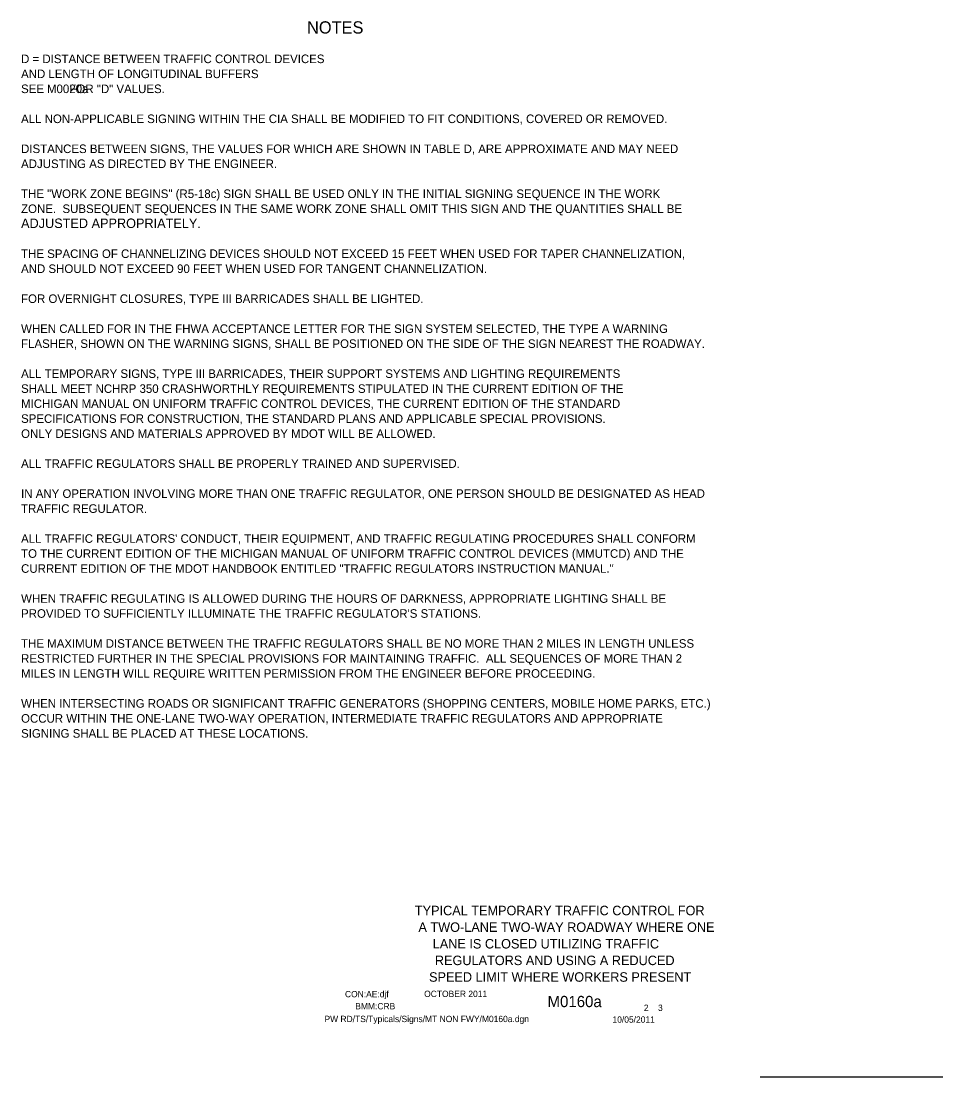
# Model space of a CAD drawing. Extents: x 16735 to 19510, y 5880 to 6929.
# Drawn here: x 17802 to 18706, y 5880 to 6915 of the extents above; entities that cross this region are included whole.
import ezdxf

# ---------------------------------------------------------------- set-up
doc = ezdxf.new("R2010")
doc.units = 0
doc.layers.add('Level 10', color=7, linetype='Continuous')
doc.layers.add('TRAFFIC_SIGNS_PR', color=7, linetype='Continuous')

msp = doc.modelspace()

# ---------------------------------------------------------------- linework, layer by layer
at = {"layer": 'TRAFFIC_SIGNS_PR'}
msp.add_line((18526.8, 5880), (18705.8, 5880), dxfattribs=at)

# ---------------------------------------------------------------- texts
at = {"layer": 'Level 10'}
for s, height, p in [('TYPICAL TEMPORARY TRAFFIC CONTROL FOR', 9.3, (18188.2, 6038.5)), ('A TWO-LANE TWO-WAY ROADWAY WHERE ONE', 9.3, (18191.7, 6022.2)), ('LANE IS CLOSED UTILIZING TRAFFIC', 9.3, (18205.7, 6005.9)), ('  REGULATORS AND USING A REDUCED ', 9.3, (18200.9, 5989.6)), ('SPEED LIMIT WHERE WORKERS PRESENT', 9.3, (18202.1, 5973.3)), ('CON:AE:djf', 6.2, (18119.7, 5958.1)), ('    OCTOBER 2011    ', 6.2, (18188.1, 5958.3)), ('    M0160a   ', 11, (18301.9, 5948.4)), ('BMM:CRB   ', 6.2, (18129.8, 5946.2)), (' 2    3 ', 6.2, (18410.4, 5944.7)), ('PW RD/TS/Typicals/Signs/MT NON FWY/M0160a.dgn    ', 6.2, (18099.6, 5933.7)), ('10/05/2011    ', 6.2, (18381.9, 5933.1))]:
    msp.add_text(s, height=height, dxfattribs=at).set_placement(p)
at = {"layer": 'TRAFFIC_SIGNS_PR'}
for s, height, p in [('NOTES', 12, (18082.5, 6903.1)), ('D = DISTANCE BETWEEN TRAFFIC CONTROL DEVICES', 8.4, (17802.2, 6874.1)), ('AND LENGTH OF LONGITUDINAL BUFFERS', 8.4, (17802.2, 6859.4)), ('SEE        FOR "D" VALUES.', 8.4, (17802.2, 6844.7)), ('M0020a', 8.4, (17827.6, 6844.7)), ('ALL NON-APPLICABLE SIGNING WITHIN THE CIA SHALL BE MODIFIED TO FIT CONDITIONS, COVERED OR REMOVED.', 8.4, (17802.2, 6815.3)), ('DISTANCES BETWEEN SIGNS, THE VALUES FOR WHICH ARE SHOWN IN TABLE D, ARE APPROXIMATE AND MAY NEED', 8.4, (17802.2, 6785.9)), ('ADJUSTING AS DIRECTED BY THE ENGINEER.', 8.4, (17802.2, 6771.2)), ('THE "WORK ZONE BEGINS" (R5-18c) SIGN SHALL BE USED ONLY IN THE INITIAL SIGNING SEQUENCE IN THE WORK', 8.4, (17802.2, 6741.8)), ('ZONE.  SUBSEQUENT SEQUENCES IN THE SAME WORK ZONE SHALL OMIT THIS SIGN AND THE QUANTITIES SHALL BE', 8.4, (17802.2, 6727.1)), ('ADJUSTED APPROPRIATELY.', 9.3, (17802.2, 6712.4)), ('THE SPACING OF CHANNELIZING DEVICES SHOULD NOT EXCEED 15 FEET WHEN USED FOR TAPER CHANNELIZATION,', 8.4, (17802.2, 6683)), ('AND SHOULD NOT EXCEED 90 FEET WHEN USED FOR TANGENT CHANNELIZATION.', 8.4, (17802.2, 6668.3)), ('FOR OVERNIGHT CLOSURES, TYPE III BARRICADES SHALL BE LIGHTED.', 8.4, (17802.2, 6638.9)), ('WHEN CALLED FOR IN THE FHWA ACCEPTANCE LETTER FOR THE SIGN SYSTEM SELECTED, THE TYPE A WARNING ', 8.4, (17802.2, 6609.5)), ('FLASHER, SHOWN ON THE WARNING SIGNS, SHALL BE POSITIONED ON THE SIDE OF THE SIGN NEAREST THE ROADWAY.', 8.4, (17802.2, 6594.8)), ('ALL TEMPORARY SIGNS, TYPE III BARRICADES, THEIR SUPPORT SYSTEMS AND LIGHTING REQUIREMENTS', 8.4, (17802.2, 6565.4)), ('SHALL MEET NCHRP 350 CRASHWORTHLY REQUIREMENTS STIPULATED IN THE CURRENT EDITION OF THE', 8.4, (17802.2, 6550.7)), ('MICHIGAN MANUAL ON UNIFORM TRAFFIC CONTROL DEVICES, THE CURRENT EDITION OF THE STANDARD', 8.4, (17802.2, 6536)), ('SPECIFICATIONS FOR CONSTRUCTION, THE STANDARD PLANS AND APPLICABLE SPECIAL PROVISIONS.', 8.4, (17802.2, 6521.3)), ('ONLY DESIGNS AND MATERIALS APPROVED BY MDOT WILL BE ALLOWED.', 8.4, (17802.2, 6506.6)), ('ALL TRAFFIC REGULATORS SHALL BE PROPERLY TRAINED AND SUPERVISED.', 8.4, (17802.2, 6477.2)), ('IN ANY OPERATION INVOLVING MORE THAN ONE TRAFFIC REGULATOR, ONE PERSON SHOULD BE DESIGNATED AS HEAD', 8.4, (17802.2, 6447.8)), ('TRAFFIC REGULATOR.', 8.4, (17802.2, 6433.1)), ("ALL TRAFFIC REGULATORS' CONDUCT, THEIR EQUIPMENT, AND TRAFFIC REGULATING PROCEDURES SHALL CONFORM", 8.4, (17802.2, 6403.7)), ('TO THE CURRENT EDITION OF THE MICHIGAN MANUAL OF UNIFORM TRAFFIC CONTROL DEVICES (MMUTCD) AND THE', 8.4, (17802.2, 6389)), ('CURRENT EDITION OF THE MDOT HANDBOOK ENTITLED "TRAFFIC REGULATORS INSTRUCTION MANUAL."', 8.4, (17802.2, 6374.3)), ('WHEN TRAFFIC REGULATING IS ALLOWED DURING THE HOURS OF DARKNESS, APPROPRIATE LIGHTING SHALL BE', 8.4, (17802.2, 6344.9)), ("PROVIDED TO SUFFICIENTLY ILLUMINATE THE TRAFFIC REGULATOR'S STATIONS.", 8.4, (17802.2, 6330.2)), ('THE MAXIMUM DISTANCE BETWEEN THE TRAFFIC REGULATORS SHALL BE NO MORE THAN 2 MILES IN LENGTH UNLESS', 8.4, (17802.2, 6300.8)), ('RESTRICTED FURTHER IN THE SPECIAL PROVISIONS FOR MAINTAINING TRAFFIC.  ALL SEQUENCES OF MORE THAN 2', 8.4, (17802.2, 6286.1)), ('MILES IN LENGTH WILL REQUIRE WRITTEN PERMISSION FROM THE ENGINEER BEFORE PROCEEDING.', 8.4, (17802.2, 6271.4)), ('WHEN INTERSECTING ROADS OR SIGNIFICANT TRAFFIC GENERATORS (SHOPPING CENTERS, MOBILE HOME PARKS, ETC.)', 8.4, (17802.2, 6242)), ('OCCUR WITHIN THE ONE-LANE TWO-WAY OPERATION, INTERMEDIATE TRAFFIC REGULATORS AND APPROPRIATE', 8.4, (17802.2, 6227.3)), ('SIGNING SHALL BE PLACED AT THESE LOCATIONS.', 8.4, (17802.2, 6212.6))]:
    msp.add_text(s, height=height, dxfattribs=at).set_placement(p)

doc.saveas('drawing.dxf')
